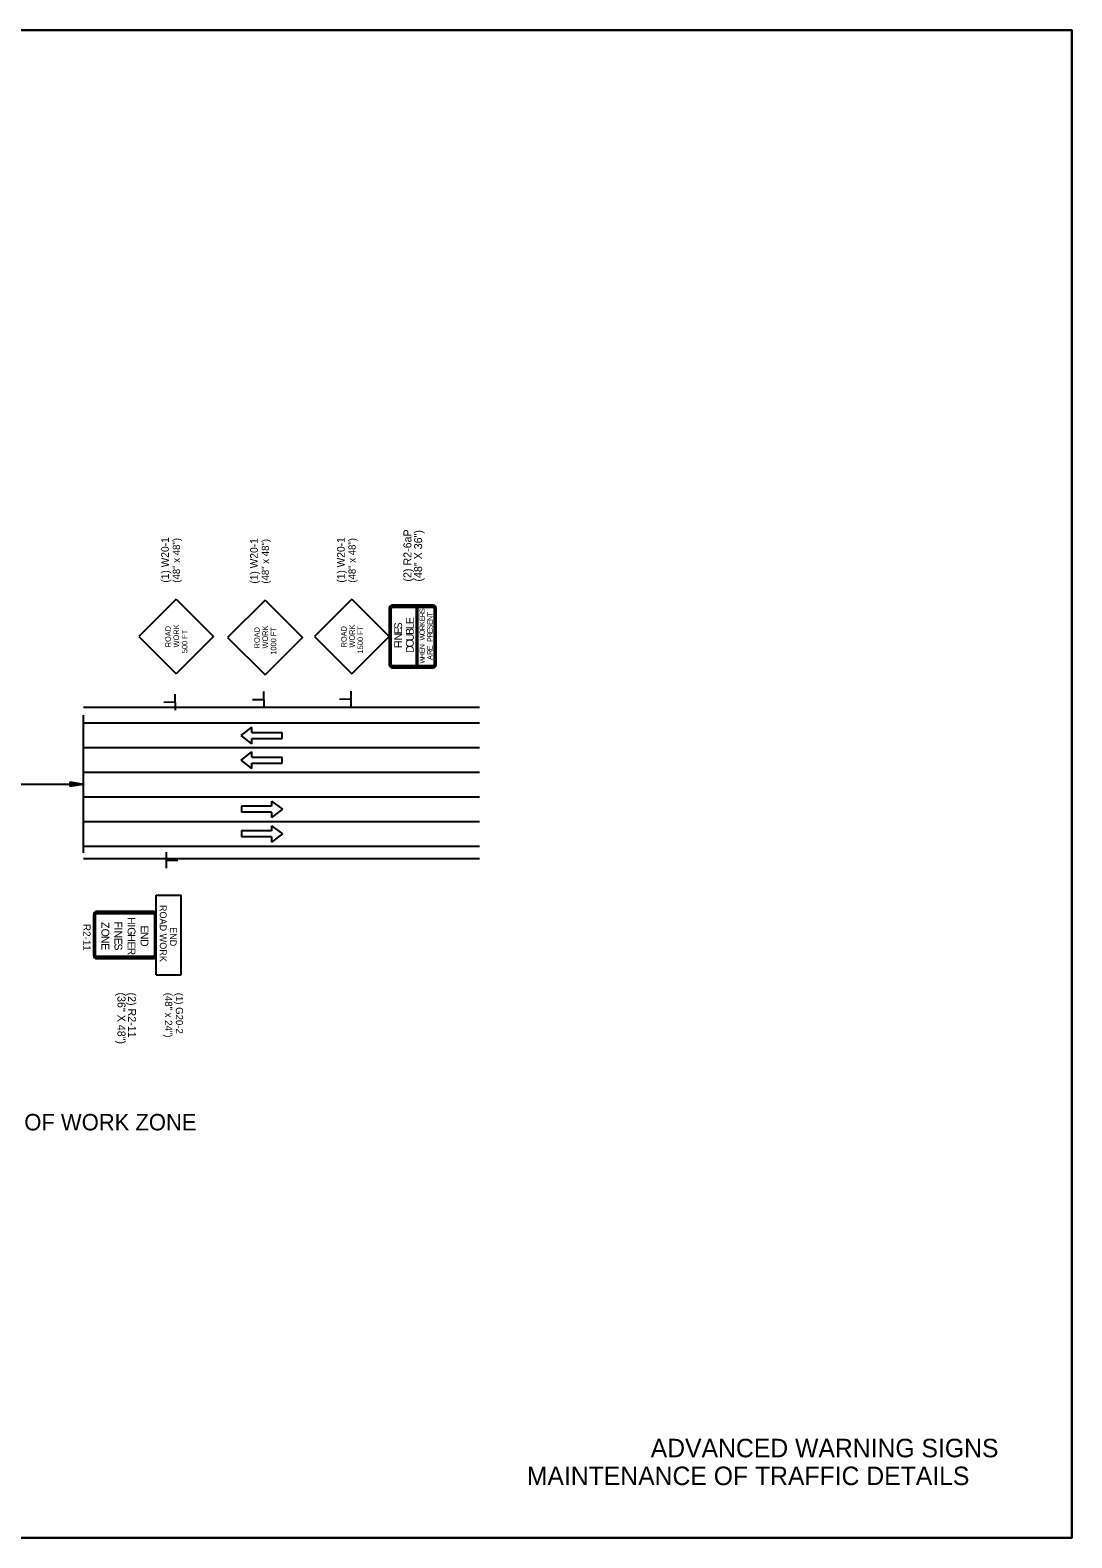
# Model space of a CAD drawing. Extents: x 32485 to 39285, y 55121 to 58033.
# Drawn here: x 38520 to 39280, y 55121 to 56221 of the extents above; entities that cross this region are included whole.
import ezdxf

# ---------------------------------------------------------------- set-up
doc = ezdxf.new("R2010")
doc.units = 0
for name, color, linetype in [('Default', 7, 'Continuous'), ('DSN_DRFT_Junk-No-Plot', 7, 'Continuous'), ('R_Border', 7, 'Continuous'), ('R_Draft', 7, 'Continuous'), ('R_Exist Surface', 7, 'Continuous'), ('R_MOT', 7, 'Continuous')]:
    doc.layers.add(name, color=color, linetype=linetype)

msp = doc.modelspace()

# ---------------------------------------------------------------- linework, layer by layer
at = {"layer": 'Default'}
for p, q in [((38781.8, 55799), (38781.8, 55757.6)), ((38782.4, 55799), (38782.4, 55757.6)), ((38783.2, 55757.6), (38783.2, 55799)), ((38813.9, 55801.1), (38784, 55801.1)), ((38813.9, 55800.5), (38784, 55800.5)), ((38784, 55799.7), (38813.9, 55799.7)), ((38801.6, 55756.9), (38801.6, 55799.7)), ((38801.6, 55799.7), (38802.5, 55799.7)), ((38802.5, 55799.7), (38802.5, 55756.9)), ((38814.7, 55799), (38814.7, 55757.6)), ((38815.5, 55757.6), (38815.5, 55799)), ((38816.1, 55757.6), (38816.1, 55799)), ((38813.9, 55756.9), (38784, 55756.9)), ((38784, 55756), (38813.9, 55756)), ((38784, 55755.4), (38813.9, 55755.4)), ((38802.5, 55756.9), (38801.6, 55756.9)), ((38558.8, 55620.4), (38558.8, 55721)), ((38673.8, 55706.1), (38681.5, 55712.1)), ((38681.5, 55700.1), (38673.8, 55706.1)), ((38681.5, 55708.4), (38681.5, 55712.1)), ((38681.5, 55708.4), (38703.6, 55708.4)), ((38703.6, 55703.9), (38703.6, 55708.4)), ((38673.8, 55688.1), (38681.5, 55694.1)), ((38681.5, 55703.9), (38703.6, 55703.9)), ((38681.5, 55700.1), (38681.5, 55703.9)), ((38681.5, 55690.4), (38681.5, 55694.1)), ((38681.5, 55682.1), (38673.8, 55688.1)), ((38681.5, 55690.4), (38703.6, 55690.4)), ((38681.5, 55685.9), (38703.6, 55685.9)), ((38681.5, 55682.1), (38681.5, 55685.9)), ((38703.6, 55685.9), (38703.6, 55690.4)), ((38301, 55670.7), (38558.8, 55670.7)), ((38696, 55654.6), (38673.9, 55654.6)), ((38673.9, 55654.6), (38673.9, 55650.1)), ((38696, 55650.1), (38673.9, 55650.1)), ((38696, 55658.3), (38696, 55654.6)), ((38696, 55658.3), (38703.8, 55652.3)), ((38703.8, 55652.3), (38696, 55646.3)), ((38696, 55650.1), (38696, 55646.3)), ((38696, 55640.3), (38696, 55636.6)), ((38696, 55640.3), (38703.8, 55634.3)), ((38696, 55636.6), (38673.9, 55636.6)), ((38673.9, 55636.6), (38673.9, 55632.1)), ((38696, 55632.1), (38673.9, 55632.1)), ((38703.8, 55634.3), (38696, 55628.3)), ((38696, 55632.1), (38696, 55628.3)), ((38566.1, 55575.5), (38566.1, 55545.5)), ((38566.7, 55575.5), (38566.7, 55545.5)), ((38567.5, 55545.5), (38567.5, 55575.5)), ((38609.7, 55577.7), (38568.3, 55577.7)), ((38609.7, 55577.1), (38568.3, 55577.1)), ((38568.3, 55576.2), (38609.7, 55576.2)), ((38610.4, 55575.5), (38610.4, 55545.5)), ((38611.2, 55545.5), (38611.2, 55575.5)), ((38611.8, 55545.5), (38611.8, 55575.5)), ((38609.7, 55544.8), (38568.3, 55544.8)), ((38568.3, 55544), (38609.7, 55544)), ((38568.3, 55543.4), (38609.7, 55543.4))]:
    msp.add_line(p, q, dxfattribs=at)
msp.add_lwpolyline([(37579.9, 56220.7), (37579.9, 55120.7), (39279.9, 55120.7), (39279.9, 56220.7)], close=True, dxfattribs=at)
for centre, radius, start, end in [((38784, 55799), 2.14, 90, 180), ((38784, 55799), 1.55, 90, 180), ((38784, 55799), 0.714, 90, 180), ((38813.9, 55799), 2.14, 0, 90), ((38813.9, 55799), 1.55, 0, 90), ((38813.9, 55799), 0.714, 0, 90), ((38784, 55757.6), 2.14, 180, 270), ((38784, 55757.6), 1.55, 180, 270), ((38784, 55757.6), 0.714, 180, 270), ((38813.9, 55757.6), 2.14, 270, 0), ((38813.9, 55757.6), 1.55, 270, 0), ((38813.9, 55757.6), 0.714, 270, 0), ((38568.3, 55575.5), 2.14, 90, 180), ((38568.3, 55575.5), 1.55, 90, 180), ((38568.3, 55575.5), 0.714, 90, 180), ((38609.7, 55575.5), 2.14, 0, 90), ((38609.7, 55575.5), 1.55, 0, 90), ((38609.7, 55575.5), 0.714, 0, 90), ((38568.3, 55545.5), 2.14, 180, 270), ((38568.3, 55545.5), 1.55, 180, 270), ((38568.3, 55545.5), 0.714, 180, 270), ((38609.7, 55545.5), 2.14, 270, 0), ((38609.7, 55545.5), 1.55, 270, 0), ((38609.7, 55545.5), 0.714, 270, 0)]:
    msp.add_arc(centre, radius, start, end, dxfattribs=at)
at = {"layer": 'DSN_DRFT_Junk-No-Plot'}
msp.add_lwpolyline([(37579.9, 56220.7), (39279.9, 56220.7), (39279.9, 55120.7), (37579.9, 55120.7)], close=True, dxfattribs=at)
at = {"layer": 'R_Border'}
for p, q in [((38626.3, 55805.6), (38599, 55778.4)), ((38626.3, 55805.6), (38653.6, 55778.4)), ((38691.2, 55804.9), (38663.9, 55777.6)), ((38691.2, 55804.9), (38718.5, 55777.6)), ((38754.6, 55805.6), (38727.3, 55778.3)), ((38754.6, 55805.6), (38781.8, 55778.3)), ((38599, 55778.4), (38626.3, 55751.1)), ((38653.6, 55778.4), (38626.3, 55751.1)), ((38663.9, 55777.6), (38691.2, 55750.3)), ((38718.5, 55777.6), (38691.2, 55750.3)), ((38727.3, 55778.3), (38754.6, 55751)), ((38781.8, 55778.3), (38754.6, 55751)), ((38690.1, 55738.1), (38690.3, 55726.3)), ((38753.7, 55738.4), (38753.9, 55726.6)), ((38625.3, 55730.4), (38617.3, 55730.2)), ((38625.4, 55736.2), (38625.6, 55724.5)), ((38690, 55732.2), (38682, 55732.1)), ((38753.7, 55732.5), (38745.6, 55732.4)), ((38619.3, 55609.3), (38619.2, 55621.1)), ((38619.4, 55615.2), (38627.5, 55615.2)), ((38611.8, 55531.6), (38611.8, 55589.5)), ((38611.8, 55589.5), (38630, 55589.5)), ((38630, 55531.6), (38630, 55589.5)), ((38611.8, 55531.6), (38630, 55531.6))]:
    msp.add_line(p, q, dxfattribs=at)
at = {"layer": 'R_Draft'}
for p, q in [((38548.8, 55672.2), (38558.8, 55670.7)), ((38548.8, 55672.2), (38548.8, 55669.2)), ((38548.8, 55672), (38557.1, 55670.7)), ((38548.8, 55671.7), (38555.4, 55670.7)), ((38548.8, 55671.5), (38553.7, 55670.7)), ((38548.8, 55671.2), (38552, 55670.7)), ((38548.8, 55671), (38550.4, 55670.7)), ((38548.8, 55669.2), (38558.8, 55670.7)), ((38548.8, 55670.2), (38552, 55670.7)), ((38548.8, 55669.7), (38555.4, 55670.7)), ((38548.8, 55669.5), (38557.1, 55670.7)), ((38548.8, 55670), (38553.7, 55670.7)), ((38548.8, 55670.5), (38550.4, 55670.7))]:
    msp.add_line(p, q, dxfattribs=at)
at = {"layer": 'R_Exist Surface'}
for p, q in [((38558.8, 55726.8), (38847.6, 55726.8)), ((38558.8, 55715.3), (38847.6, 55715.3)), ((38558.8, 55697.3), (38847.6, 55697.3)), ((38558.8, 55679.3), (38847.6, 55679.3)), ((38558.8, 55661.3), (38847.6, 55661.3)), ((38558.8, 55643.3), (38847.6, 55643.3)), ((38558.8, 55625.3), (38847.6, 55625.3)), ((38558.8, 55616.3), (38847.6, 55616.3))]:
    msp.add_line(p, q, dxfattribs=at)

# ---------------------------------------------------------------- texts
at = {"layer": 'Default'}
for s, height, rotation, p in [('E', 5.71, 90, (38799.7, 55787.4)), ('S', 3.81, 90, (38807.7, 55795.4)), ('R', 3.81, 90, (38807.7, 55792.4)), ('E', 3.81, 90, (38807.7, 55789.4)), ('T', 3.81, 90, (38813.4, 55793)), ('N', 3.81, 90, (38813.4, 55789.8)), ('S', 5.71, 90, (38791.2, 55783.6)), ('E', 5.71, 90, (38791.2, 55780)), ('L', 5.71, 90, (38799.7, 55783.6)), ('B', 5.71, 90, (38799.7, 55779.5)), ('O', 3.81, 90, (38807.7, 55779.3)), ('K', 3.81, 90, (38807.7, 55786.1)), ('R', 3.81, 90, (38807.7, 55782.9)), ('S', 3.81, 90, (38813.4, 55783.6)), ('E', 3.81, 90, (38813.4, 55786.8)), ('E', 3.81, 90, (38813.4, 55780.8)), ('R', 3.81, 90, (38813.4, 55777.6)), ('N', 5.71, 90, (38791.2, 55775.5)), ('I', 5.71, 90, (38791.2, 55773.5)), ('F', 5.71, 90, (38791.2, 55769.8)), ('O', 5.71, 90, (38799.7, 55770.5)), ('U', 5.71, 90, (38799.7, 55775)), ('D', 5.71, 90, (38799.7, 55766.3)), ('W', 3.81, 90, (38807.7, 55775.4)), ('N', 3.81, 90, (38807.7, 55769)), ('P', 3.81, 90, (38813.4, 55774.4)), ('E', 3.81, 90, (38813.4, 55768.3)), ('E', 3.81, 90, (38807.7, 55766)), ('H', 3.81, 90, (38807.7, 55762.5)), ('W', 3.81, 90, (38807.7, 55758.6)), ('R', 3.81, 90, (38813.4, 55765)), ('A', 3.81, 90, (38813.4, 55761.2)), ('H', 5.71, 270, (38590.9, 55573.6)), ('R2-11', 5.38, 270, (38558.5, 55568.6)), ('O', 5.71, 270, (38571.8, 55565.2)), ('Z', 5.71, 270, (38571.8, 55570)), ('F', 5.71, 270, (38581.3, 55570.5)), ('I', 5.71, 270, (38581.3, 55566.1)), ('N', 5.71, 270, (38581.3, 55563.8)), ('G', 5.71, 270, (38590.9, 55566.2)), ('I', 5.71, 270, (38590.9, 55568.4)), ('E', 5.71, 270, (38600.4, 55567.4)), ('N', 5.71, 270, (38600.4, 55562.8)), ('N', 5.71, 270, (38571.8, 55559.9)), ('E', 5.71, 270, (38571.8, 55554.6)), ('E', 5.71, 270, (38581.3, 55558.6)), ('S', 5.71, 270, (38581.3, 55554.4)), ('H', 5.71, 270, (38590.9, 55561.1)), ('E', 5.71, 270, (38590.9, 55555.8)), ('R', 5.71, 270, (38590.9, 55551.3)), ('D', 5.71, 270, (38600.4, 55557.6))]:
    msp.add_text(s, height=height, rotation=rotation, dxfattribs=at).set_placement(p)
msp.add_text('ADVANCE WARNING SIGNS AT BEGINNING AND END OF WORK ZONE', height=12, dxfattribs=at).set_placement((38100.9, 55418))
at = {"layer": 'R_Border'}
for s, height, rotation, p in [('(1) W20-1', 5.58, 90, (38621, 55817.6)), ('(48" x 48")', 5.233, 90, (38629.1, 55817.6)), ('(1) W20-1', 5.58, 90, (38685.9, 55816.9)), ('(48" x 48")', 5.233, 90, (38694, 55816.9)), ('(1) W20-1', 5.58, 90, (38749.3, 55817.6)), ('(48" x 48")', 5.233, 90, (38757.3, 55817.6)), ('ROAD', 4.02, 90.0004, (38622.4, 55770.5)), ('WORK', 4.02, 90, (38628.4, 55770.4)), (' 500 FT', 4.02, 90.0006, (38634.5, 55764.7)), ('ROAD', 4.02, 90.0004, (38687.3, 55769.7)), ('WORK', 4.02, 90, (38693.3, 55769.6)), ('1000 FT', 4.02, 90.0006, (38699.4, 55765.1)), ('ROAD', 4.02, 90.0004, (38750.7, 55770.4)), ('WORK', 4.02, 90, (38756.7, 55770.3)), ('1500 FT', 4.02, 90.0006, (38762.7, 55766)), ('ROAD WORK', 4.95, 270, (38614.4, 55582.5)), ('END', 4.95, 270, (38621.7, 55566.3)), ('(48" x 24")', 5.233, 270, (38618.2, 55518.4)), ('(1) G20-2', 5.23, 270, (38626.1, 55518.4))]:
    msp.add_text(s, height=height, rotation=rotation, dxfattribs=at).set_placement(p)
at = {"layer": 'R_Draft'}
for s, rotation, p in [('(2) R2-6aP', 90, (38798, 55818.4)), ('(48" X 36")', 90, (38805.8, 55818.4)), ('(36" X 48")', 270, (38583.5, 55518.6)), ('(2) R2-11', 270, (38591.2, 55518.6))]:
    msp.add_text(s, height=5.83, rotation=rotation, dxfattribs=at).set_placement(p)
at = {"layer": 'R_MOT'}
for s, p in [('ADVANCED WARNING SIGNS', (38972.6, 55179.5)), ('MAINTENANCE OF TRAFFIC DETAILS', (38882.2, 55159.2))]:
    msp.add_text(s, height=13.5, dxfattribs=at).set_placement(p)

doc.saveas('drawing.dxf')
